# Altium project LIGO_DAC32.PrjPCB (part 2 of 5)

## Sheet LD32_FPGA.SchDoc: FPGA Top
size C; SheetNumber: 8; SheetTotal: 17
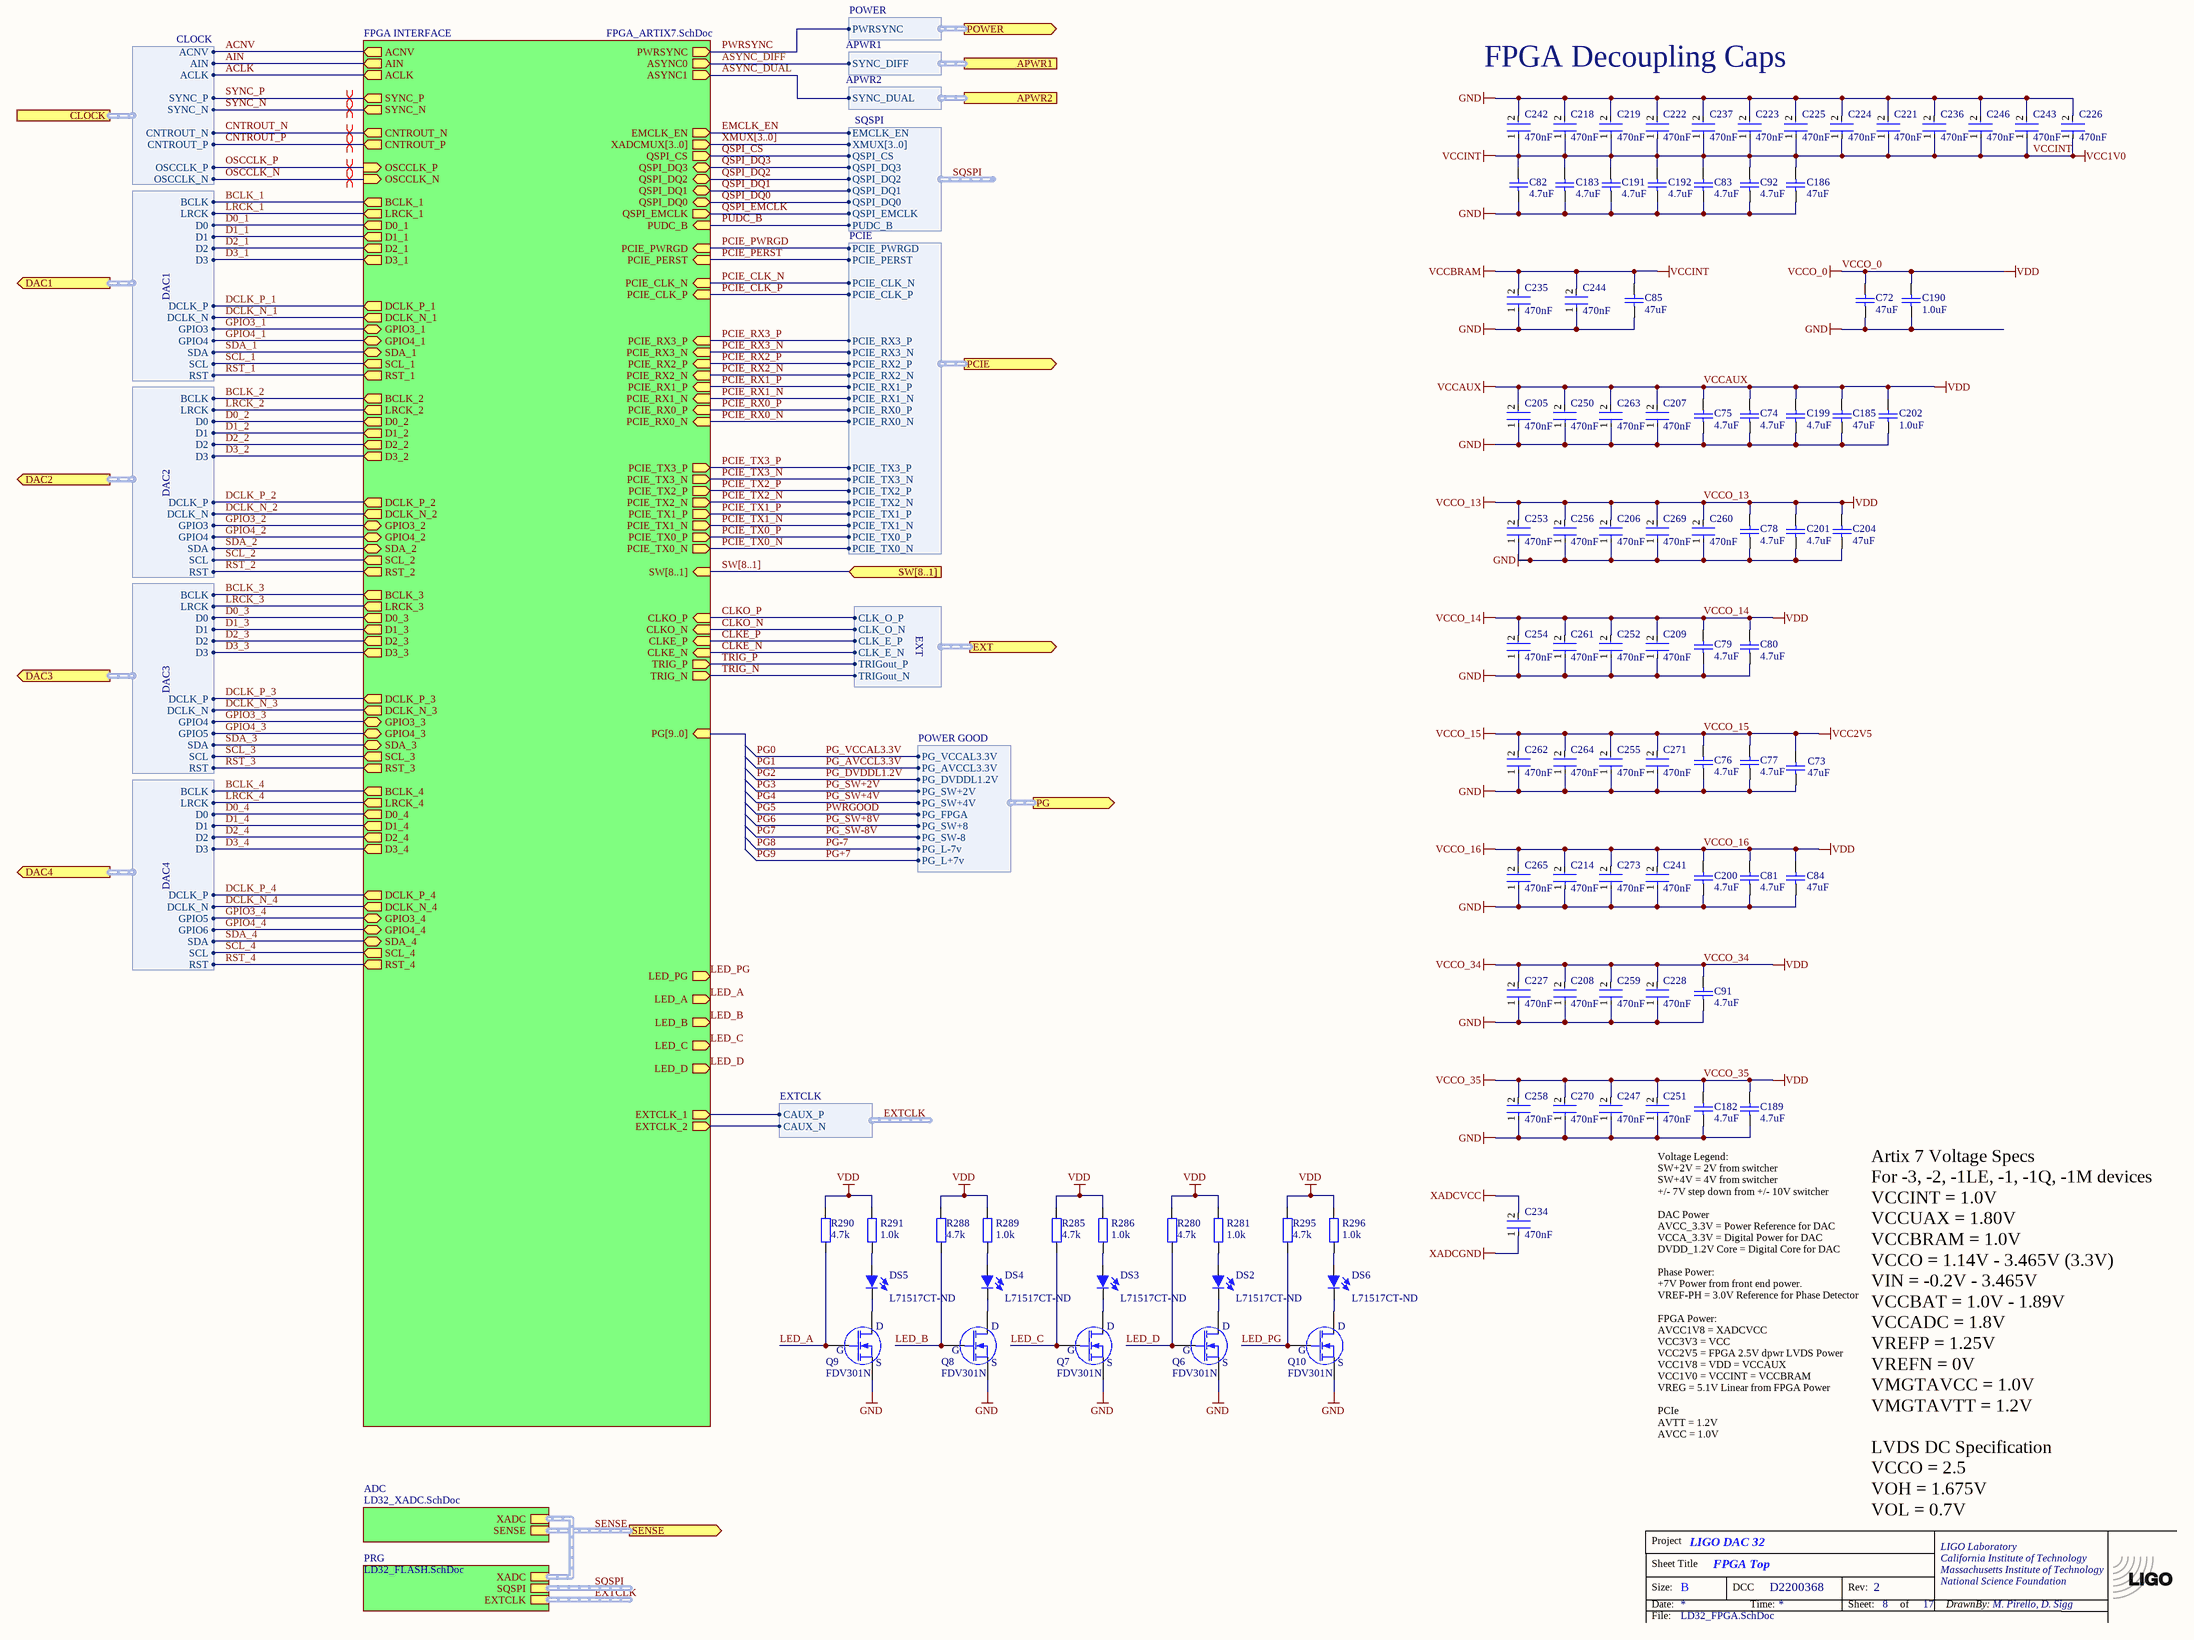
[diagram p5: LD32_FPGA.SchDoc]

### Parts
(Parts that share a designator on the sheet are numbered #1, #2 ... from top to bottom, then left to right.)
*?#3  TitleBlock  (value not drawn)  (graphical)
C72  47uF  [CC3216-1206]
C73  47uF  [CC3216-1206]
C74  4.7uF  [CC1608-0603]
C75  4.7uF  [CC1608-0603]
C76  4.7uF  [CC1608-0603]
C77  4.7uF  [CC1608-0603]
C78  4.7uF  [CC1608-0603]
C79  4.7uF  [CC1608-0603]
C80  4.7uF  [CC1608-0603]
C81  4.7uF  [CC1608-0603]
C82  4.7uF  [CC1608-0603]
C83  4.7uF  [CC1608-0603]
C84  47uF  [CC3216-1206]
C85  47uF  [CC3216-1206]
C91  4.7uF  [CC1608-0603]
C92  4.7uF  [CC1608-0603]
C182  4.7uF  [CC1608-0603]
C183  4.7uF  [CC1608-0603]
C185  47uF  [CC3216-1206]
C186  47uF  [CC3216-1206]
C189  4.7uF  [CC1608-0603]
C190  1.0uF  [CC1608-0603]
C191  4.7uF  [CC1608-0603]
C192  4.7uF  [CC1608-0603]
C199  4.7uF  [CC1608-0603]
C200  4.7uF  [CC1608-0603]
C201  4.7uF  [CC1608-0603]
C202  1.0uF  [CC1608-0603]
C204  47uF  [CC3216-1206]
C205  470nF  [FP-CL03-IPC_B]
C206  470nF  [FP-CL03-IPC_B]
C207  470nF  [FP-CL03-IPC_B]
C208  470nF  [FP-CL03-IPC_B]
C209  470nF  [FP-CL03-IPC_B]
C214  470nF  [FP-CL03-IPC_B]
C218  470nF  [FP-CL03-IPC_B]
C219  470nF  [FP-CL03-IPC_B]
C221  470nF  [FP-CL03-IPC_B]
C222  470nF  [FP-CL03-IPC_B]
C223  470nF  [FP-CL03-IPC_B]
C224  470nF  [FP-CL03-IPC_B]
C225  470nF  [FP-CL03-IPC_B]
C226  470nF  [FP-CL03-IPC_B]
C227  470nF  [FP-CL03-IPC_B]
C228  470nF  [FP-CL03-IPC_B]
C234  470nF  [FP-CL03-IPC_B]
C235  470nF  [FP-CL03-IPC_B]
C236  470nF  [FP-CL03-IPC_B]
C237  470nF  [FP-CL03-IPC_B]
C241  470nF  [FP-CL03-IPC_B]
C242  470nF  [FP-CL03-IPC_B]
C243  470nF  [FP-CL03-IPC_B]
C244  470nF  [FP-CL03-IPC_B]
C246  470nF  [FP-CL03-IPC_B]
C247  470nF  [FP-CL03-IPC_B]
C250  470nF  [FP-CL03-IPC_B]
C251  470nF  [FP-CL03-IPC_B]
C252  470nF  [FP-CL03-IPC_B]
C253  470nF  [FP-CL03-IPC_B]
C254  470nF  [FP-CL03-IPC_B]
C255  470nF  [FP-CL03-IPC_B]
C256  470nF  [FP-CL03-IPC_B]
C258  470nF  [FP-CL03-IPC_B]
C259  470nF  [FP-CL03-IPC_B]
C260  470nF  [FP-CL03-IPC_B]
C261  470nF  [FP-CL03-IPC_B]
C262  470nF  [FP-CL03-IPC_B]
C263  470nF  [FP-CL03-IPC_B]
C264  470nF  [FP-CL03-IPC_B]
C265  470nF  [FP-CL03-IPC_B]
C269  470nF  [FP-CL03-IPC_B]
C270  470nF  [FP-CL03-IPC_B]
C271  470nF  [FP-CL03-IPC_B]
C273  470nF  [FP-CL03-IPC_B]
DS2  Supplier Part Number 1: L71517CT-ND  [LED-0805]  (hidden comment: LED)
DS3  Supplier Part Number 1: L71517CT-ND  [LED-0805]  (hidden comment: LED)
DS4  Supplier Part Number 1: L71517CT-ND  [LED-0805]  (hidden comment: LED)
DS5  Supplier Part Number 1: L71517CT-ND  [LED-0805]  (hidden comment: LED)
DS6  Supplier Part Number 1: L71517CT-ND  [LED-0805]  (hidden comment: LED)
Q6  FDV301N  [SO-G3/C2.25]
Q7  FDV301N  [SO-G3/C2.25]
Q8  FDV301N  [SO-G3/C2.25]
Q9  FDV301N  [SO-G3/C2.25]
Q10  FDV301N  [SO-G3/C2.25]
R280  4.7k  [CR1005-0402]
R281  1.0k  [CR1005-0402]
R285  4.7k  [CR1005-0402]
R286  1.0k  [CR1005-0402]
R288  4.7k  [CR1005-0402]
R289  1.0k  [CR1005-0402]
R290  4.7k  [CR1005-0402]
R291  1.0k  [CR1005-0402]
R295  4.7k  [CR1005-0402]
R296  1.0k  [CR1005-0402]

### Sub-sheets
ADC = LD32_XADC.SchDoc: XADC (harness XADC), SENSE (harness SENSE)
FPGA INTERFACE = FPGA_ARTIX7.SchDoc: SW[8..1] (in), XADCMUX[3..0] (out), PWRSYNC (out), QSPI_DQ0 (bidir), QSPI_CS (out), QSPI_DQ2 (bidir), QSPI_DQ3 (bidir), QSPI_DQ1 (bidir), QSPI_EMCLK (out), PUDC_B (in), EMCLK_EN (out), PCIE_PWRGD (in), PCIE_PERST (in), PCIE_CLK_N (in), PCIE_CLK_P (in), PCIE_RX0_N (in), PCIE_TX0_P (out), PCIE_RX0_P (in), PCIE_TX0_N (out), PCIE_TX3_P (out), PCIE_TX2_P (out), PCIE_TX1_P (out), PCIE_TX3_N (out), PCIE_TX2_N (out), PCIE_TX1_N (out), PCIE_RX1_P (in), PCIE_RX2_P (in), PCIE_RX3_P (in), PCIE_RX1_N (in), PCIE_RX2_N (in), PCIE_RX3_N (in), ACNV (out), AIN (out), ACLK (out), SYNC_P (out), SYNC_N (out), CNTROUT_N (out), CNTROUT_P (out), OSCCLK_P (in), OSCCLK_N (in), BCLK_1 (out), LRCK_1 (out), D0_1 (out), DCLK_P_1 (out), DCLK_N_1 (out), SDA_1 (bidir), SCL_1 (out), RST_1 (out), GPIO4_1 (bidir), GPIO3_1 (bidir), D1_1 (out), D2_1 (out), D3_1 (out), BCLK_2 (out), LRCK_2 (out), D0_2 (out), DCLK_P_2 (out), DCLK_N_2 (out), SDA_2 (bidir), SCL_2 (out), RST_2 (out), GPIO4_2 (bidir), GPIO3_2 (bidir), D1_2 (out), D2_2 (out), D3_2 (out), BCLK_3 (out), LRCK_3 (out), D0_3 (out), DCLK_P_3 (out), DCLK_N_3 (out), SDA_3 (bidir), SCL_3 (out), RST_3 (out), GPIO4_3 (bidir), GPIO3_3 (bidir), D1_3 (out), D2_3 (out), D3_3 (out), BCLK_4 (out), LRCK_4 (out), D0_4 (out), DCLK_P_4 (out), DCLK_N_4 (out), SDA_4 (bidir), SCL_4 (out), RST_4 (out), GPIO4_4 (bidir), GPIO3_4 (bidir), D1_4 (out), D2_4 (out), D3_4 (out), CLKO_P (in), CLKO_N (in), CLKE_P (in), CLKE_N (in), TRIG_P (out), TRIG_N (out), ASYNC0 (out), ASYNC1 (out), PG[9..0] (in), LED_A (out), LED_PG (out), LED_B (out), LED_C (out), LED_D (out), EXTCLK_1 (out), EXTCLK_2 (out)
PRG = LD32_FLASH.SchDoc: SQSPI (harness SQSPI), XADC (harness XADC), EXTCLK (harness SQSPI)

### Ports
APWR1 (harness APWR1), APWR2 (harness APWR2), CLOCK (harness CLOCK), DAC1 (out, harness DAC1), DAC2 (out, harness DAC2), DAC3 (out, harness DAC3), DAC4 (out, harness DAC4), EXT (out, harness EXT), PCIE (out, harness PCIE), PG (out, harness Power good), POWER (out, harness POWER), SENSE (out, harness Power good), SW[8..1] (in)

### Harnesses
SQSPI: QSPI_CS, QSPI_DQ3, QSPI_DQ2, QSPI_DQ1, QSPI_DQ0, QSPI_EMCLK, PUDC_B, XMUX[3..0], EMCLK_EN
DAC1: BCLK, LRCK, D0, D1, D2, D3, SCL, SDA, RST, GPIO4, GPIO3, DCLK_N, DCLK_P
DAC2: BCLK, LRCK, D0, D1, D2, D3, SCL, SDA, RST, GPIO4, GPIO3, DCLK_N, DCLK_P
DAC3: BCLK, LRCK, D1, D2, D3, SCL, SDA, RST, GPIO5, GPIO4, DCLK_N, DCLK_P, D0
DAC4: BCLK, LRCK, D2, D3, SCL, SDA, RST, GPIO6, GPIO5, DCLK_N, DCLK_P, D1, D0
APWR1: SYNC_DIFF
APWR2: SYNC_DUAL
POWER GOOD: PG_VCCAL3.3V, PG_AVCCL3.3V, PG_DVDDL1.2V, PG_SW+2V, PG_SW+4V, PG_FPGA, PG_SW+8, PG_SW-8, PG_L-7v, PG_L+7v
CLOCK: OSCCLK_N, OSCCLK_P, CNTROUT_N, CNTROUT_P, SYNC_N, SYNC_P, ACLK, ACNV, AIN
PCIE: PCIE_CLK_N, PCIE_CLK_P, PCIE_RX0_N, PCIE_RX0_P, PCIE_TX0_N, PCIE_TX0_P, PCIE_PERST, PCIE_PWRGD, PCIE_TX1_N, PCIE_TX1_P, PCIE_TX2_P, PCIE_TX2_N, PCIE_TX3_P, PCIE_TX3_N, PCIE_RX1_N, PCIE_RX1_P, PCIE_RX2_N, PCIE_RX2_P, PCIE_RX3_N, PCIE_RX3_P
EXT: CLK_O_N, CLK_E_P, CLK_E_N, CLK_O_P, TRIGout_P, TRIGout_N
POWER: PWRSYNC
EXTCLK: CAUX_P, CAUX_N

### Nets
GND: C72.1 C73.1 C74.1 C75.1 C76.1 C77.1 C78.1 C79.1 C80.1 C81.1 C82.1 C83.1 C84.1 C85.1 C91.1 C92.1 C182.1 C183.1 C185.1 C186.1 C189.1 C190.1 C191.1 C192.1 C199.1 C200.1 C201.1 C202.1 C204.1 C205.1 C206.1 C207.1 C208.1 C209.1 C214.1 C218.2 C219.2 C221.2 C222.2 C223.2 C224.2 C225.2 C226.2 C227.1 C228.1 C235.1 C236.2 C237.2 C241.1 C242.2 C243.2 C244.1 C246.2 C247.1 C250.1 C251.1 C252.1 C253.1 C254.1 C255.1 C256.1 C258.1 C259.1 C260.1 C261.1 C262.1 C263.1 C264.1 C265.1 C269.1 C270.1 C271.1 C273.1 Q6.2(S) Q7.2(S) Q8.2(S) Q9.2(S) Q10.2(S)
VCC1V0: C82.2 C83.2 C85.2 C92.2 C183.2 C186.2 C191.2 C192.2 C218.1 C219.1 C221.1 C222.1 C223.1 C224.1 C225.1 C226.1 C235.2 C236.1 C237.1 C242.1 C243.1 C244.2 C246.1  [also labelled VCCBRAM, VCCINT]
VCC2V5: C73.2 C76.2 C77.2 C255.2 C262.2 C264.2 C271.2  [also labelled VCCO_15]
VCCAUX: C72.2 C74.2 C75.2 C78.2 C79.2 C80.2 C81.2 C84.2 C91.2 C182.2 C185.2 C189.2 C190.2 C199.2 C200.2 C201.2 C202.2 C204.2 C205.2 C206.2 C207.2 C208.2 C209.2 C214.2 C227.2 C228.2 C241.2 C247.2 C250.2 C251.2 C252.2 C253.2 C254.2 C256.2 C258.2 C259.2 C260.2 C261.2 C263.2 C265.2 C269.2 C270.2 C273.2 R280.2 R281.1 R285.2 R286.1 R288.2 R289.1 R290.2 R291.1 R295.2 R296.1  [also labelled VCCO_0, VCCO_13, VCCO_14, VCCO_16, VCCO_34, VCCO_35, VDD]
XADCGND: C234.1
XADCVCC: C234.2
ACLK: sheet FPGA INTERFACE/ACLK, port CLOCK.ACLK  [project net CLOCK.ACLK]
ACNV: sheet FPGA INTERFACE/ACNV, port CLOCK.ACNV  [project net CLOCK.ACNV]
AIN: sheet FPGA INTERFACE/AIN, port CLOCK.AIN  [project net CLOCK.AIN]
ASYNC_DIFF: sheet FPGA INTERFACE/ASYNC0, port APWR1.SYNC_DIFF  [project net APWR1.SYNC_DIFF]
ASYNC_DUAL: sheet FPGA INTERFACE/ASYNC1, port APWR2.SYNC_DUAL  [project net APWR2.SYNC_DUAL]
BCLK_1: sheet FPGA INTERFACE/BCLK_1, port DAC1.BCLK  [project net DAC1.BCLK]
BCLK_2: sheet FPGA INTERFACE/BCLK_2, port DAC2.BCLK  [project net DAC2.BCLK]
BCLK_3: sheet FPGA INTERFACE/BCLK_3, port DAC3.BCLK  [project net DAC3.BCLK]
BCLK_4: sheet FPGA INTERFACE/BCLK_4, port DAC4.BCLK  [project net DAC4.BCLK]
CLKE_N: sheet FPGA INTERFACE/CLKE_N, port EXT.CLK_E_N
CLKE_P: sheet FPGA INTERFACE/CLKE_P, port EXT.CLK_E_P
CLKO_N: sheet FPGA INTERFACE/CLKO_N, port EXT.CLK_O_N
CLKO_P: sheet FPGA INTERFACE/CLKO_P, port EXT.CLK_O_P
CNTROUT_N: sheet FPGA INTERFACE/CNTROUT_N, port CLOCK.CNTROUT_N  [project net CLOCK.CNTROUT_N]
CNTROUT_P: sheet FPGA INTERFACE/CNTROUT_P, port CLOCK.CNTROUT_P  [project net CLOCK.CNTROUT_P]
D0_1: sheet FPGA INTERFACE/D0_1, port DAC1.D0  [project net DAC1.D0]
D0_2: sheet FPGA INTERFACE/D0_2, port DAC2.D0  [project net DAC2.D0]
D0_3: sheet FPGA INTERFACE/D0_3, port DAC3.D0  [project net DAC3.D0]
D0_4: sheet FPGA INTERFACE/D0_4, port DAC4.D0  [project net DAC4.D0]
D1_1: sheet FPGA INTERFACE/D1_1, port DAC1.D1  [project net DAC1.D1]
D1_2: sheet FPGA INTERFACE/D1_2, port DAC2.D1  [project net DAC2.D1]
D1_3: sheet FPGA INTERFACE/D1_3, port DAC3.D1  [project net DAC3.D1]
D1_4: sheet FPGA INTERFACE/D1_4, port DAC4.D1  [project net DAC4.D1]
D2_1: sheet FPGA INTERFACE/D2_1, port DAC1.D2  [project net DAC1.D2]
D2_2: sheet FPGA INTERFACE/D2_2, port DAC2.D2  [project net DAC2.D2]
D2_3: sheet FPGA INTERFACE/D2_3, port DAC3.D2  [project net DAC3.D2]
D2_4: sheet FPGA INTERFACE/D2_4, port DAC4.D2  [project net DAC4.D2]
D3_1: sheet FPGA INTERFACE/D3_1, port DAC1.D3  [project net DAC1.D3]
D3_2: sheet FPGA INTERFACE/D3_2, port DAC2.D3  [project net DAC2.D3]
D3_3: sheet FPGA INTERFACE/D3_3, port DAC3.D3  [project net DAC3.D3]
D3_4: sheet FPGA INTERFACE/D3_4, port DAC4.D3  [project net DAC4.D3]
DCLK_N_1: sheet FPGA INTERFACE/DCLK_N_1, port DAC1.DCLK_N  [project net DAC1.DCLK_N]
DCLK_N_2: sheet FPGA INTERFACE/DCLK_N_2, port DAC2.DCLK_N  [project net DAC2.DCLK_N]
DCLK_N_3: sheet FPGA INTERFACE/DCLK_N_3, port DAC3.DCLK_N  [project net DAC3.DCLK_N]
DCLK_N_4: sheet FPGA INTERFACE/DCLK_N_4, port DAC4.DCLK_N  [project net DAC4.DCLK_N]
DCLK_P_1: sheet FPGA INTERFACE/DCLK_P_1, port DAC1.DCLK_P  [project net DAC1.DCLK_P]
DCLK_P_2: sheet FPGA INTERFACE/DCLK_P_2, port DAC2.DCLK_P  [project net DAC2.DCLK_P]
DCLK_P_3: sheet FPGA INTERFACE/DCLK_P_3, port DAC3.DCLK_P  [project net DAC3.DCLK_P]
DCLK_P_4: sheet FPGA INTERFACE/DCLK_P_4, port DAC4.DCLK_P  [project net DAC4.DCLK_P]
EMCLK_EN: sheet FPGA INTERFACE/EMCLK_EN, sheet PRG/SQSPI.EMCLK_EN  [project net SQSPI.EMCLK_EN]
EXTCLK.CAUX_N: sheet FPGA INTERFACE/EXTCLK_2, sheet PRG/EXTCLK.CAUX_N
EXTCLK.CAUX_P: sheet FPGA INTERFACE/EXTCLK_1, sheet PRG/EXTCLK.CAUX_P
GPIO3_1: sheet FPGA INTERFACE/GPIO3_1, port DAC1.GPIO3  [project net DAC1.GPIO3_]
GPIO3_2: sheet FPGA INTERFACE/GPIO3_2, port DAC2.GPIO3  [project net DAC2.GPIO3_]
GPIO3_3: sheet FPGA INTERFACE/GPIO3_3, port DAC3.GPIO4  [project net DAC3.GPIO4_]
GPIO3_4: sheet FPGA INTERFACE/GPIO3_4, port DAC4.GPIO5  [project net DAC4.GPIO5]
GPIO4_1: sheet FPGA INTERFACE/GPIO4_1, port DAC1.GPIO4  [project net DAC1.GPIO4_]
GPIO4_2: sheet FPGA INTERFACE/GPIO4_2, port DAC2.GPIO4  [project net DAC2.GPIO4_]
GPIO4_3: sheet FPGA INTERFACE/GPIO4_3, port DAC3.GPIO5  [project net DAC3.GPIO5]
GPIO4_4: sheet FPGA INTERFACE/GPIO4_4, port DAC4.GPIO6  [project net DAC4.GPIO6]
LED_A: Q9.1(G) R290.1 ; sheet FPGA INTERFACE/LED_A
LED_B: Q8.1(G) R288.1 ; sheet FPGA INTERFACE/LED_B
LED_C: Q7.1(G) R285.1 ; sheet FPGA INTERFACE/LED_C
LED_D: Q6.1(G) R280.1 ; sheet FPGA INTERFACE/LED_D
LED_PG: Q10.1(G) R295.1 ; sheet FPGA INTERFACE/LED_PG
LRCK_1: sheet FPGA INTERFACE/LRCK_1, port DAC1.LRCK  [project net DAC1.LRCK]
LRCK_2: sheet FPGA INTERFACE/LRCK_2, port DAC2.LRCK  [project net DAC2.LRCK]
LRCK_3: sheet FPGA INTERFACE/LRCK_3, port DAC3.LRCK  [project net DAC3.LRCK]
LRCK_4: sheet FPGA INTERFACE/LRCK_4, port DAC4.LRCK  [project net DAC4.LRCK]
OSCCLK_N: sheet FPGA INTERFACE/OSCCLK_N, port CLOCK.OSCCLK_N  [project net CLOCK.OSCCLK_N]
OSCCLK_P: sheet FPGA INTERFACE/OSCCLK_P, port CLOCK.OSCCLK_P  [project net CLOCK.OSCCLK_P]
PCIE_CLK_N: sheet FPGA INTERFACE/PCIE_CLK_N, port PCIE.PCIE_CLK_N  [project net PCIE.PCIE_CLK_N]
PCIE_CLK_P: sheet FPGA INTERFACE/PCIE_CLK_P, port PCIE.PCIE_CLK_P  [project net PCIE.PCIE_CLK_P]
PCIE_PERST: sheet FPGA INTERFACE/PCIE_PERST, port PCIE.PCIE_PERST  [project net PCIE.PCIE_PERST]
PCIE_PWRGD: sheet FPGA INTERFACE/PCIE_PWRGD, port PCIE.PCIE_PWRGD  [project net PCIE.PCIE_PWRGD]
PCIE_RX0_N: sheet FPGA INTERFACE/PCIE_RX0_N, port PCIE.PCIE_RX0_N  [project net PCIE.PCIE_RX0_N]
PCIE_RX0_P: sheet FPGA INTERFACE/PCIE_RX0_P, port PCIE.PCIE_RX0_P  [project net PCIE.PCIE_RX0_P]
PCIE_RX1_N: sheet FPGA INTERFACE/PCIE_RX1_N, port PCIE.PCIE_RX1_N  [project net PCIE.PCIE_RX1_N]
PCIE_RX1_P: sheet FPGA INTERFACE/PCIE_RX1_P, port PCIE.PCIE_RX1_P  [project net PCIE.PCIE_RX1_P]
PCIE_RX2_N: sheet FPGA INTERFACE/PCIE_RX2_N, port PCIE.PCIE_RX2_N  [project net PCIE.PCIE_RX2_N]
PCIE_RX2_P: sheet FPGA INTERFACE/PCIE_RX2_P, port PCIE.PCIE_RX2_P  [project net PCIE.PCIE_RX2_P]
PCIE_RX3_N: sheet FPGA INTERFACE/PCIE_RX3_N, port PCIE.PCIE_RX3_N  [project net PCIE.PCIE_RX3_N]
PCIE_RX3_P: sheet FPGA INTERFACE/PCIE_RX3_P, port PCIE.PCIE_RX3_P  [project net PCIE.PCIE_RX3_P]
PCIE_TX0_N: sheet FPGA INTERFACE/PCIE_TX0_N, port PCIE.PCIE_TX0_N  [project net PCIE.PCIE_TX0_N]
PCIE_TX0_P: sheet FPGA INTERFACE/PCIE_TX0_P, port PCIE.PCIE_TX0_P  [project net PCIE.PCIE_TX0_P]
PCIE_TX1_N: sheet FPGA INTERFACE/PCIE_TX1_N, port PCIE.PCIE_TX1_N  [project net PCIE.PCIE_TX1_N]
PCIE_TX1_P: sheet FPGA INTERFACE/PCIE_TX1_P, port PCIE.PCIE_TX1_P  [project net PCIE.PCIE_TX1_P]
PCIE_TX2_N: sheet FPGA INTERFACE/PCIE_TX2_N, port PCIE.PCIE_TX2_N  [project net PCIE.PCIE_TX2_N]
PCIE_TX2_P: sheet FPGA INTERFACE/PCIE_TX2_P, port PCIE.PCIE_TX2_P  [project net PCIE.PCIE_TX2_P]
PCIE_TX3_N: sheet FPGA INTERFACE/PCIE_TX3_N, port PCIE.PCIE_TX3_N  [project net PCIE.PCIE_TX3_N]
PCIE_TX3_P: sheet FPGA INTERFACE/PCIE_TX3_P, port PCIE.PCIE_TX3_P  [project net PCIE.PCIE_TX3_P]
PUDC_B: sheet FPGA INTERFACE/PUDC_B, sheet PRG/SQSPI.PUDC_B  [project net SQSPI.PUDC_B]
PWRSYNC: sheet FPGA INTERFACE/PWRSYNC, port POWER.PWRSYNC  [project net POWER.PWRSYNC]
QSPI_CS: sheet FPGA INTERFACE/QSPI_CS, sheet PRG/SQSPI.QSPI_CS  [project net SQSPI.QSPI_CS]
QSPI_DQ0: sheet FPGA INTERFACE/QSPI_DQ0, sheet PRG/SQSPI.QSPI_DQ0  [project net SQSPI.QSPI_DQ0]
QSPI_DQ1: sheet FPGA INTERFACE/QSPI_DQ1, sheet PRG/SQSPI.QSPI_DQ1  [project net SQSPI.QSPI_DQ1]
QSPI_DQ2: sheet FPGA INTERFACE/QSPI_DQ2, sheet PRG/SQSPI.QSPI_DQ2  [project net SQSPI.QSPI_DQ2]
QSPI_DQ3: sheet FPGA INTERFACE/QSPI_DQ3, sheet PRG/SQSPI.QSPI_DQ3  [project net SQSPI.QSPI_DQ3]
QSPI_EMCLK: sheet FPGA INTERFACE/QSPI_EMCLK, sheet PRG/SQSPI.QSPI_EMCLK  [project net SQSPI.QSPI_EMCLK]
RST_1: sheet FPGA INTERFACE/RST_1, port DAC1.RST  [project net DAC1.RST]
RST_2: sheet FPGA INTERFACE/RST_2, port DAC2.RST  [project net DAC2.RST]
RST_3: sheet FPGA INTERFACE/RST_3, port DAC3.RST  [project net DAC3.RST]
RST_4: sheet FPGA INTERFACE/RST_4, port DAC4.RST  [project net DAC4.RST]
SCL_1: sheet FPGA INTERFACE/SCL_1, port DAC1.SCL  [project net DAC1.SCL]
SCL_2: sheet FPGA INTERFACE/SCL_2, port DAC2.SCL  [project net DAC2.SCL]
SCL_3: sheet FPGA INTERFACE/SCL_3, port DAC3.SCL  [project net DAC3.SCL]
SCL_4: sheet FPGA INTERFACE/SCL_4, port DAC4.SCL  [project net DAC4.SCL]
SDA_1: sheet FPGA INTERFACE/SDA_1, port DAC1.SDA  [project net DAC1.SDA]
SDA_2: sheet FPGA INTERFACE/SDA_2, port DAC2.SDA  [project net DAC2.SDA]
SDA_3: sheet FPGA INTERFACE/SDA_3, port DAC3.SDA  [project net DAC3.SDA]
SDA_4: sheet FPGA INTERFACE/SDA_4, port DAC4.SDA  [project net DAC4.SDA]
SYNC_N: sheet FPGA INTERFACE/SYNC_N, port CLOCK.SYNC_N  [project net CLOCK.SYNC_N]
SYNC_P: sheet FPGA INTERFACE/SYNC_P, port CLOCK.SYNC_P  [project net CLOCK.SYNC_P]
TRIG_N: sheet FPGA INTERFACE/TRIG_N, port EXT.TRIGout_N  [project net EXT.TRIGout_N]
TRIG_P: sheet FPGA INTERFACE/TRIG_P, port EXT.TRIGout_P  [project net EXT.TRIGout_P]
NetDS2_1: DS2.1(K) Q6.3(D)
NetDS2_2: DS2.2(A) R281.2
NetDS3_1: DS3.1(K) Q7.3(D)
NetDS3_2: DS3.2(A) R286.2
NetDS4_1: DS4.1(K) Q8.3(D)
NetDS4_2: DS4.2(A) R289.2
NetDS5_1: DS5.1(K) Q9.3(D)
NetDS5_2: DS5.2(A) R291.2
NetDS6_1: DS6.1(K) Q10.3(D)
NetDS6_2: DS6.2(A) R296.2

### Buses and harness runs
bus SW[8..1] = port SW[8..1] = sheet FPGA INTERFACE/SW[8..1]
bus XMUX[3..0] = sheet FPGA INTERFACE/XADCMUX[3..0]
harness EXTCLK = sheet PRG/EXTCLK
harness SENSE = port SENSE = sheet ADC/SENSE
harness sheet ADC/XADC = sheet PRG/XADC
harness SQSPI = sheet PRG/SQSPI

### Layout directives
differential pair: CLOCK.CNTROUT_N, CLOCK.CNTROUT_P, CLOCK.OSCCLK_N, CLOCK.OSCCLK_P, CLOCK.SYNC_N, CLOCK.SYNC_P

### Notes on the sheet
- FPGA Decoupling Caps
- Voltage Legend:
  SW+2V = 2V from switcher
  SW+4V = 4V from switcher
  +/- 7V step down from +/- 10V switcher
  DAC Power
  AVCC_3.3V = Power Reference for DAC
  VCCA_3.3V = Digital Power for DAC
  DVDD_1.2V Core = Digital Core for DAC
  Phase Power:
  +7V Power from front end power.
  VREF-PH = 3.0V Reference for Phase Detector
  FPGA Power:
  AVCC1V8 = XADCVCC
  VCC3V3 = VCC
  VCC2V5 = FPGA 2.5V dpwr LVDS Power
  VCC1V8 = VDD = VCCAUX
  VCC1V0 = VCCINT = VCCBRAM
  VREG = 5.1V Linear from FPGA Power
  PCIe
  AVTT = 1.2V
  AVCC = 1.0V
- Artix 7 Voltage Specs
  For -3, -2, -1LE, -1, -1Q, -1M devices
  VCCINT = 1.0V
  VCCUAX = 1.80V
  VCCBRAM = 1.0V
  VCCO = 1.14V - 3.465V (3.3V)
  VIN = -0.2V - 3.465V
  VCCBAT = 1.0V - 1.89V
  VCCADC = 1.8V
  VREFP = 1.25V
  VREFN = 0V
  VMGTAVCC = 1.0V
  VMGTAVTT = 1.2V
  LVDS DC Specification
  VCCO = 2.5
  VOH = 1.675V
  VOL = 0.7V

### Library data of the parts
C72 C73 C84 C85 C185 C186 C204 = ChipCap: C1206 47uF; Part Number: C3216X5R1E476M160DC
C74-C83 C91 C92 C182 C183 C189 C191 C192 C199-C201 = ChipCap: C0603 4.7uF; Part Number: CL10B475KQ8NQNC
C190 C202 = ChipCap: C0603 1.0uF; Part Number: CL10B105KA8NNNC
C205-C209 C214 C218 C219 C221-C228 C234-C237 C241-C244 C246 C247 C250-C256 C258-C265 C269-C271 C273 = CMP-2010-00306-2: Cap Ceramic 470nF 4V X5R ±20% Pad SMD 0201 +85°C T/R; Part Number: LMK063BBJ474MPLF
DS2-DS6 = LED: Panel mount LED
Q6-Q10 = FDV301N: FDV301N, Digital FET, N-channel, SOT23; Part Number: FDV301NCT-ND
R280 R285 R288 R290 R295 = ChipRes1: R0402 4.7k; Part Number: ERA-2AED472X
R281 R286 R289 R291 R296 = ChipRes1: R0402 1.0k; Part Number: ERA-2AEB102X

## Sheet FPGA_ARTIX7.SchDoc: FPGA
size C; Organization: Altium Limited; Address1: L3, 12a Rodborough Rd; Address2: Frenchs Forest; Address3: NSW; Address4: Australia 2086; SheetNumber: 11; SheetTotal: 17
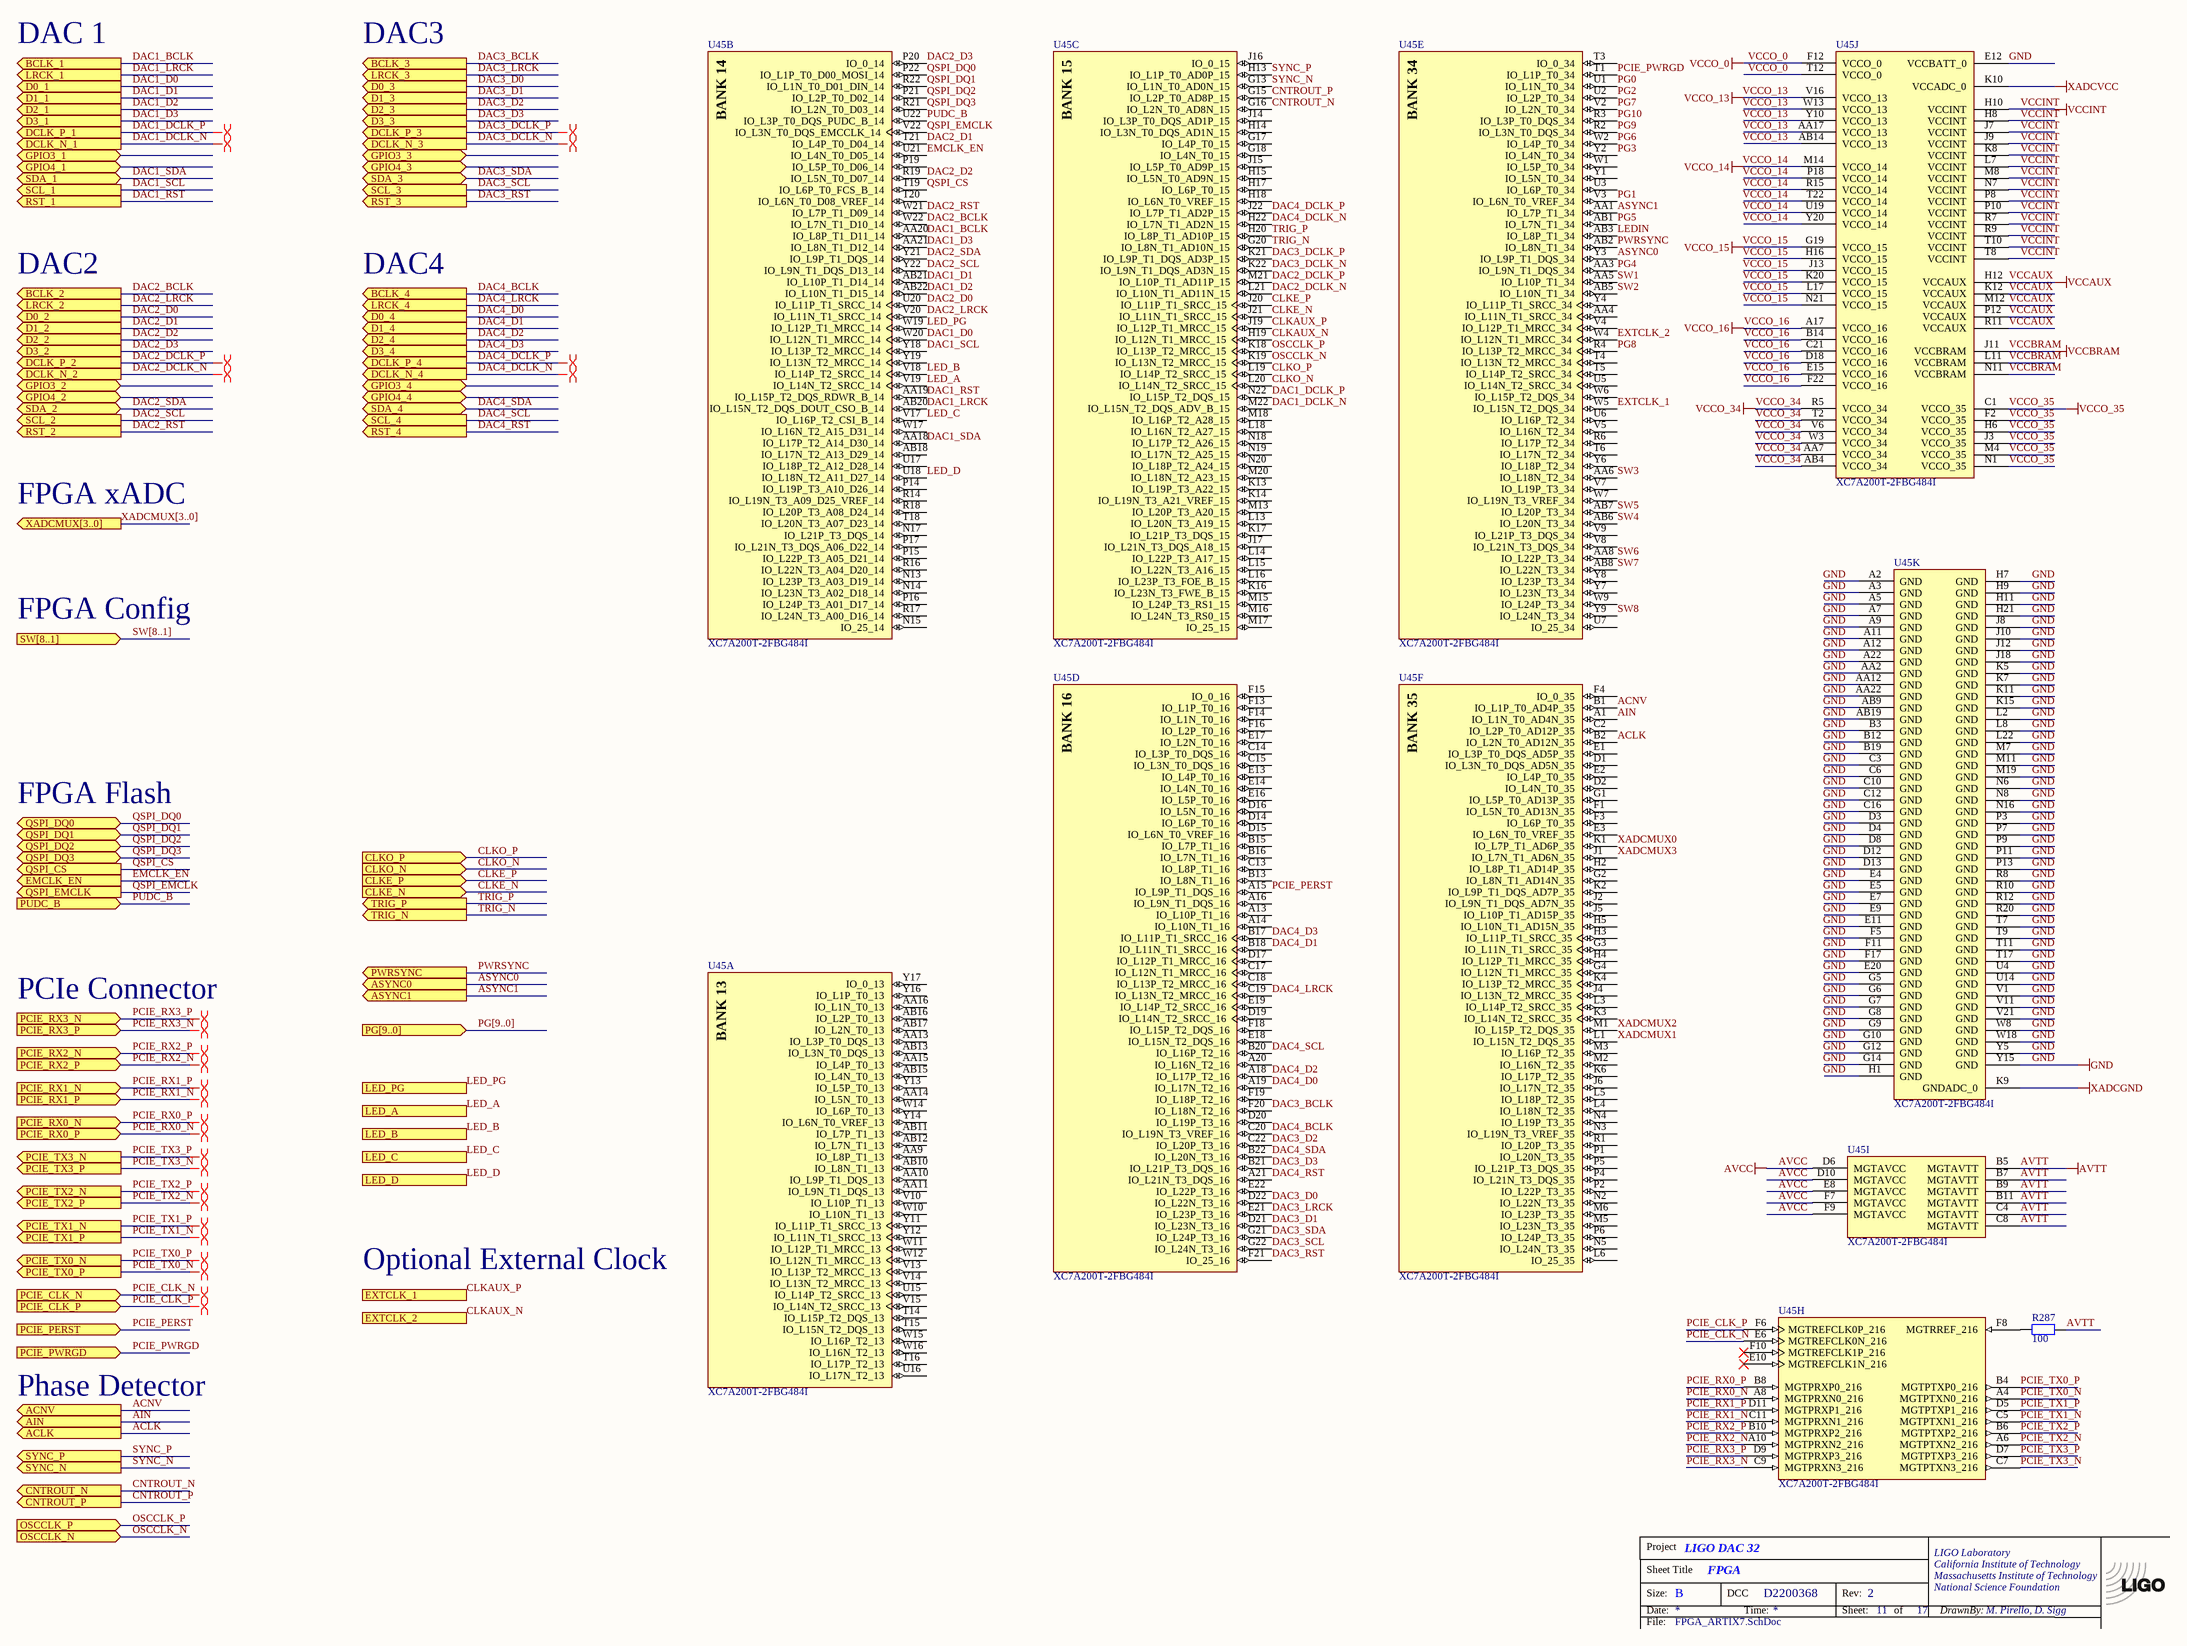
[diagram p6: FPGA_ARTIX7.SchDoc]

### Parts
(Parts that share a designator on the sheet are numbered #1, #2 ... from top to bottom, then left to right.)
*?#4  TitleBlock  (value not drawn)  (graphical)
R287  100  [CR1005-0402]
U45  XC7A200T-2FBG484I  [FBG484]  (parts A,B,C,D,E,F,H,I,J,K of 11)

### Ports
ACLK (out), ACNV (out), AIN (out), ASYNC0 (out), ASYNC1 (out), BCLK_1 (out), BCLK_2 (out), BCLK_3 (out), BCLK_4 (out), CLKE_N (in), CLKE_P (in), CLKO_N (in), CLKO_P (in), CNTROUT_N (out), CNTROUT_P (out), D0_1 (out), D0_2 (out), D0_3 (out), D0_4 (out), D1_1 (out), D1_2 (out), D1_3 (out), D1_4 (out), D2_1 (out), D2_2 (out), D2_3 (out), D2_4 (out), D3_1 (out), D3_2 (out), D3_3 (out), D3_4 (out), DCLK_N_1 (out), DCLK_N_2 (out), DCLK_N_3 (out), DCLK_N_4 (out), DCLK_P_1 (out), DCLK_P_2 (out), DCLK_P_3 (out), DCLK_P_4 (out), EMCLK_EN (out), EXTCLK_1 (out), EXTCLK_2 (out), GPIO3_1 (bidir), GPIO3_2 (bidir), GPIO3_3 (bidir), GPIO3_4 (bidir), GPIO4_1 (bidir), GPIO4_2 (bidir), GPIO4_3 (bidir), GPIO4_4 (bidir), LED_A (out), LED_B (out), LED_C (out), LED_D (out), LED_PG (out), LRCK_1 (out), LRCK_2 (out), LRCK_3 (out), LRCK_4 (out), OSCCLK_N (in), OSCCLK_P (in), PCIE_CLK_N (in), PCIE_CLK_P (in), PCIE_PERST (in), PCIE_PWRGD (in), PCIE_RX0_N (in), PCIE_RX0_P (in), PCIE_RX1_N (in), PCIE_RX1_P (in), PCIE_RX2_N (in), PCIE_RX2_P (in), PCIE_RX3_N (in), PCIE_RX3_P (in), PCIE_TX0_N (out), PCIE_TX0_P (out), PCIE_TX1_N (out), PCIE_TX1_P (out), PCIE_TX2_N (out), PCIE_TX2_P (out), PCIE_TX3_N (out), PCIE_TX3_P (out), PG[9..0] (in), PUDC_B (in), PWRSYNC (out), QSPI_CS (out), QSPI_DQ0 (bidir), QSPI_DQ1 (bidir), QSPI_DQ2 (bidir), QSPI_DQ3 (bidir), QSPI_EMCLK (out), RST_1 (out), RST_2 (out), RST_3 (out), RST_4 (out), SCL_1 (out), SCL_2 (out), SCL_3 (out), SCL_4 (out), SDA_1 (bidir), SDA_2 (bidir), SDA_3 (bidir), SDA_4 (bidir), SW[8..1] (in), SYNC_N (out), SYNC_P (out), TRIG_N (out), TRIG_P (out), XADCMUX[3..0] (out)

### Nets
AVCC: U45.D6(MGTAVCC) U45.D10(MGTAVCC) U45.E8(MGTAVCC) U45.F7(MGTAVCC) U45.F9(MGTAVCC)
AVTT: R287.2 U45.B5(MGTAVTT) U45.B7(MGTAVTT) U45.B9(MGTAVTT) U45.B11(MGTAVTT) U45.C4(MGTAVTT) U45.C8(MGTAVTT)
GND: U45.A2(GND) U45.A3(GND) U45.A5(GND) U45.A7(GND) U45.A9(GND) U45.A11(GND) U45.A12(GND) U45.A22(GND) U45.AA2(GND) U45.AA12(GND) U45.AA22(GND) U45.AB9(GND) U45.AB19(GND) U45.B3(GND) U45.B12(GND) U45.B19(GND) U45.C3(GND) U45.C6(GND) U45.C10(GND) U45.C12(GND) U45.C16(GND) U45.D3(GND) U45.D4(GND) U45.D8(GND) U45.D12(GND) U45.D13(GND) U45.E4(GND) U45.E5(GND) U45.E7(GND) U45.E9(GND) U45.E11(GND) U45.E12(VCCBATT_0) U45.E20(GND) U45.F5(GND) U45.F11(GND) U45.F17(GND) U45.G5(GND) U45.G6(GND) U45.G7(GND) U45.G8(GND) U45.G9(GND) U45.G10(GND) U45.G12(GND) U45.G14(GND) U45.H1(GND) U45.H7(GND) U45.H9(GND) U45.H11(GND) U45.H21(GND) U45.J8(GND) U45.J10(GND) U45.J12(GND) U45.J18(GND) U45.K5(GND) U45.K7(GND) U45.K11(GND) U45.K15(GND) U45.L2(GND) U45.L8(GND) U45.L22(GND) U45.M7(GND) U45.M11(GND) U45.M19(GND) U45.N6(GND) U45.N8(GND) U45.N16(GND) U45.P3(GND) U45.P7(GND) U45.P9(GND) U45.P11(GND) U45.P13(GND) U45.R8(GND) U45.R10(GND) U45.R12(GND) U45.R20(GND) U45.T7(GND) U45.T9(GND) U45.T11(GND) U45.T17(GND) U45.U4(GND) U45.U14(GND) U45.V1(GND) U45.V11(GND) U45.V21(GND) U45.W8(GND) U45.W18(GND) U45.Y5(GND) U45.Y15(GND)
VCCAUX: U45.A17(VCCO_16) U45.AA7(VCCO_34) U45.AA17(VCCO_13) U45.AB4(VCCO_34) U45.AB14(VCCO_13) U45.B14(VCCO_16) U45.C1(VCCO_35) U45.C21(VCCO_16) U45.D18(VCCO_16) U45.E15(VCCO_16) U45.F2(VCCO_35) U45.F12(VCCO_0) U45.F22(VCCO_16) U45.H6(VCCO_35) U45.H12(VCCAUX) U45.J3(VCCO_35) U45.K12(VCCAUX) U45.M4(VCCO_35) U45.M12(VCCAUX) U45.M14(VCCO_14) U45.N1(VCCO_35) U45.P12(VCCAUX) U45.P18(VCCO_14) U45.R5(VCCO_34) U45.R11(VCCAUX) U45.R15(VCCO_14) U45.T2(VCCO_34) U45.T12(VCCO_0) U45.T22(VCCO_14) U45.U19(VCCO_14) U45.V6(VCCO_34) U45.V16(VCCO_13) U45.W3(VCCO_34) U45.W13(VCCO_13) U45.Y10(VCCO_13) U45.Y20(VCCO_14)  [also labelled VCCO_0, VCCO_13, VCCO_14, VCCO_16, VCCO_34, VCCO_35]
VCCBRAM: U45.H8(VCCINT) U45.H10(VCCINT) U45.J7(VCCINT) U45.J9(VCCINT) U45.J11(VCCBRAM) U45.K8(VCCINT) U45.L7(VCCINT) U45.L11(VCCBRAM) U45.M8(VCCINT) U45.N7(VCCINT) U45.N11(VCCBRAM) U45.P8(VCCINT) U45.P10(VCCINT) U45.R7(VCCINT) U45.R9(VCCINT) U45.T8(VCCINT) U45.T10(VCCINT)  [also labelled VCCINT]  [project net VCC1V0]
VCCO_15: U45.G19(VCCO_15) U45.H16(VCCO_15) U45.J13(VCCO_15) U45.K20(VCCO_15) U45.L17(VCCO_15) U45.N21(VCCO_15)  [project net VCC2V5]
XADCGND: U45.K9(GNDADC_0)
XADCVCC: U45.K10(VCCADC_0)
ACLK: U45.B2(IO_L2N_T0_AD12N_35) ; port ACLK  [project net CLOCK.ACLK]
ACNV: U45.B1(IO_L1P_T0_AD4P_35) ; port ACNV  [project net CLOCK.ACNV]
AIN: U45.A1(IO_L1N_T0_AD4N_35) ; port AIN  [project net CLOCK.AIN]
ASYNC0: U45.Y3(IO_L9P_T1_DQS_34) ; port ASYNC0  [project net APWR1.SYNC_DIFF]
ASYNC1: U45.AA1(IO_L7P_T1_34) ; port ASYNC1  [project net APWR2.SYNC_DUAL]
CLKAUX_N: U45.H19(IO_L12N_T1_MRCC_15) ; port EXTCLK_2  [project net EXTCLK.CAUX_N]
CLKAUX_P: U45.J19(IO_L12P_T1_MRCC_15) ; port EXTCLK_1  [project net EXTCLK.CAUX_P]
CLKE_N: U45.J21(IO_L11N_T1_SRCC_15) ; port CLKE_N
CLKE_P: U45.J20(IO_L11P_T1_SRCC_15) ; port CLKE_P
CLKO_N: U45.L20(IO_L14N_T2_SRCC_15) ; port CLKO_N
CLKO_P: U45.L19(IO_L14P_T2_SRCC_15) ; port CLKO_P
CNTROUT_N: U45.G16(IO_L2N_T0_AD8N_15) ; port CNTROUT_N  [project net CLOCK.CNTROUT_N]
CNTROUT_P: U45.G15(IO_L2P_T0_AD8P_15) ; port CNTROUT_P  [project net CLOCK.CNTROUT_P]
DAC1_BCLK: U45.AA20(IO_L8P_T1_D11_14) ; port BCLK_1  [project net DAC1.BCLK]
DAC1_D0: U45.W20(IO_L12N_T1_MRCC_14) ; port D0_1  [project net DAC1.D0]
DAC1_D1: U45.AB21(IO_L10P_T1_D14_14) ; port D1_1  [project net DAC1.D1]
DAC1_D2: U45.AB22(IO_L10N_T1_D15_14) ; port D2_1  [project net DAC1.D2]
DAC1_D3: U45.AA21(IO_L8N_T1_D12_14) ; port D3_1  [project net DAC1.D3]
DAC1_DCLK_N: U45.M22(IO_L15N_T2_DQS_ADV_B_15) ; port DCLK_N_1  [project net DAC1.DCLK_N]
DAC1_DCLK_P: U45.N22(IO_L15P_T2_DQS_15) ; port DCLK_P_1  [project net DAC1.DCLK_P]
DAC1_LRCK: U45.AB20(IO_L15N_T2_DQS_DOUT_CSO_B_14) ; port LRCK_1  [project net DAC1.LRCK]
DAC1_RST: U45.AA19(IO_L15P_T2_DQS_RDWR_B_14) ; port RST_1  [project net DAC1.RST]
DAC1_SCL: U45.Y18(IO_L13P_T2_MRCC_14) ; port SCL_1  [project net DAC1.SCL]
DAC1_SDA: U45.AA18(IO_L17P_T2_A14_D30_14) ; port SDA_1  [project net DAC1.SDA]
DAC2_BCLK: U45.W22(IO_L7N_T1_D10_14) ; port BCLK_2  [project net DAC2.BCLK]
DAC2_D0: U45.U20(IO_L11P_T1_SRCC_14) ; port D0_2  [project net DAC2.D0]
DAC2_D1: U45.T21(IO_L4P_T0_D04_14) ; port D1_2  [project net DAC2.D1]
DAC2_D2: U45.R19(IO_L5N_T0_D07_14) ; port D2_2  [project net DAC2.D2]
DAC2_D3: U45.P20(IO_0_14) ; port D3_2  [project net DAC2.D3]
DAC2_DCLK_N: U45.L21(IO_L10N_T1_AD11N_15) ; port DCLK_N_2  [project net DAC2.DCLK_N]
DAC2_DCLK_P: U45.M21(IO_L10P_T1_AD11P_15) ; port DCLK_P_2  [project net DAC2.DCLK_P]
DAC2_LRCK: U45.V20(IO_L11N_T1_SRCC_14) ; port LRCK_2  [project net DAC2.LRCK]
DAC2_RST: U45.W21(IO_L7P_T1_D09_14) ; port RST_2  [project net DAC2.RST]
DAC2_SCL: U45.Y22(IO_L9N_T1_DQS_D13_14) ; port SCL_2  [project net DAC2.SCL]
DAC2_SDA: U45.Y21(IO_L9P_T1_DQS_14) ; port SDA_2  [project net DAC2.SDA]
DAC3_BCLK: U45.F20(IO_L18N_T2_16) ; port BCLK_3  [project net DAC3.BCLK]
DAC3_D0: U45.D22(IO_L22N_T3_16) ; port D0_3  [project net DAC3.D0]
DAC3_D1: U45.D21(IO_L23N_T3_16) ; port D1_3  [project net DAC3.D1]
DAC3_D2: U45.C22(IO_L20P_T3_16) ; port D2_3  [project net DAC3.D2]
DAC3_D3: U45.B21(IO_L21P_T3_DQS_16) ; port D3_3  [project net DAC3.D3]
DAC3_DCLK_N: U45.K22(IO_L9N_T1_DQS_AD3N_15) ; port DCLK_N_3  [project net DAC3.DCLK_N]
DAC3_DCLK_P: U45.K21(IO_L9P_T1_DQS_AD3P_15) ; port DCLK_P_3  [project net DAC3.DCLK_P]
DAC3_LRCK: U45.E21(IO_L23P_T3_16) ; port LRCK_3  [project net DAC3.LRCK]
DAC3_RST: U45.F21(IO_25_16) ; port RST_3  [project net DAC3.RST]
DAC3_SCL: U45.G22(IO_L24N_T3_16) ; port SCL_3  [project net DAC3.SCL]
DAC3_SDA: U45.G21(IO_L24P_T3_16) ; port SDA_3  [project net DAC3.SDA]
DAC4_BCLK: U45.C20(IO_L19N_T3_VREF_16) ; port BCLK_4  [project net DAC4.BCLK]
DAC4_D0: U45.A19(IO_L17N_T2_16) ; port D0_4  [project net DAC4.D0]
DAC4_D1: U45.B18(IO_L11N_T1_SRCC_16) ; port D1_4  [project net DAC4.D1]
DAC4_D2: U45.A18(IO_L17P_T2_16) ; port D2_4  [project net DAC4.D2]
DAC4_D3: U45.B17(IO_L11P_T1_SRCC_16) ; port D3_4  [project net DAC4.D3]
DAC4_DCLK_N: U45.H22(IO_L7N_T1_AD2N_15) ; port DCLK_N_4  [project net DAC4.DCLK_N]
DAC4_DCLK_P: U45.J22(IO_L7P_T1_AD2P_15) ; port DCLK_P_4  [project net DAC4.DCLK_P]
DAC4_LRCK: U45.C19(IO_L13N_T2_MRCC_16) ; port LRCK_4  [project net DAC4.LRCK]
DAC4_RST: U45.A21(IO_L21N_T3_DQS_16) ; port RST_4  [project net DAC4.RST]
DAC4_SCL: U45.B20(IO_L16P_T2_16) ; port SCL_4  [project net DAC4.SCL]
DAC4_SDA: U45.B22(IO_L20N_T3_16) ; port SDA_4  [project net DAC4.SDA]
EMCLK_EN: U45.U21(IO_L4N_T0_D05_14) ; port EMCLK_EN  [project net SQSPI.EMCLK_EN]
EXTCLK_1: U45.W5(IO_L15N_T2_DQS_34)
EXTCLK_2: U45.W4(IO_L12N_T1_MRCC_34)
LED_A: U45.V19(IO_L14N_T2_SRCC_14) ; port LED_A
LED_B: U45.V18(IO_L14P_T2_SRCC_14) ; port LED_B
LED_C: U45.V17(IO_L16P_T2_CSI_B_14) ; port LED_C
LED_D: U45.U18(IO_L18N_T2_A11_D27_14) ; port LED_D
LED_PG: U45.W19(IO_L12P_T1_MRCC_14) ; port LED_PG
LEDIN: U45.AB3(IO_L8P_T1_34)
OSCCLK_N: U45.K19(IO_L13N_T2_MRCC_15) ; port OSCCLK_N  [project net CLOCK.OSCCLK_N]
OSCCLK_P: U45.K18(IO_L13P_T2_MRCC_15) ; port OSCCLK_P  [project net CLOCK.OSCCLK_P]
PCIE_CLK_N: U45.E6(MGTREFCLK0N_216) ; port PCIE_CLK_N  [project net PCIE.PCIE_CLK_N]
PCIE_CLK_P: U45.F6(MGTREFCLK0P_216) ; port PCIE_CLK_P  [project net PCIE.PCIE_CLK_P]
PCIE_PERST: U45.A15(IO_L9P_T1_DQS_16) ; port PCIE_PERST  [project net PCIE.PCIE_PERST]
PCIE_PWRGD: U45.T1(IO_L1P_T0_34) ; port PCIE_PWRGD  [project net PCIE.PCIE_PWRGD]
PCIE_RX0_N: U45.A8(MGTPRXN0_216) ; port PCIE_RX0_P  [project net PCIE.PCIE_RX0_P]
PCIE_RX0_P: U45.B8(MGTPRXP0_216) ; port PCIE_RX0_N  [project net PCIE.PCIE_RX0_N]
PCIE_RX1_N: U45.C11(MGTPRXN1_216) ; port PCIE_RX1_P  [project net PCIE.PCIE_RX1_P]
PCIE_RX1_P: U45.D11(MGTPRXP1_216) ; port PCIE_RX1_N  [project net PCIE.PCIE_RX1_N]
PCIE_RX2_N: U45.A10(MGTPRXN2_216) ; port PCIE_RX2_P  [project net PCIE.PCIE_RX2_P]
PCIE_RX2_P: U45.B10(MGTPRXP2_216) ; port PCIE_RX2_N  [project net PCIE.PCIE_RX2_N]
PCIE_RX3_N: U45.C9(MGTPRXN3_216) ; port PCIE_RX3_P  [project net PCIE.PCIE_RX3_P]
PCIE_RX3_P: U45.D9(MGTPRXP3_216) ; port PCIE_RX3_N  [project net PCIE.PCIE_RX3_N]
PCIE_TX0_N: U45.A4(MGTPTXN0_216) ; port PCIE_TX0_P  [project net PCIE.PCIE_TX0_P]
PCIE_TX0_P: U45.B4(MGTPTXP0_216) ; port PCIE_TX0_N  [project net PCIE.PCIE_TX0_N]
PCIE_TX1_N: U45.C5(MGTPTXN1_216) ; port PCIE_TX1_P  [project net PCIE.PCIE_TX1_P]
PCIE_TX1_P: U45.D5(MGTPTXP1_216) ; port PCIE_TX1_N  [project net PCIE.PCIE_TX1_N]
PCIE_TX2_N: U45.A6(MGTPTXN2_216) ; port PCIE_TX2_P  [project net PCIE.PCIE_TX2_P]
PCIE_TX2_P: U45.B6(MGTPTXP2_216) ; port PCIE_TX2_N  [project net PCIE.PCIE_TX2_N]
PCIE_TX3_N: U45.C7(MGTPTXN3_216) ; port PCIE_TX3_P  [project net PCIE.PCIE_TX3_P]
PCIE_TX3_P: U45.D7(MGTPTXP3_216) ; port PCIE_TX3_N  [project net PCIE.PCIE_TX3_N]
PG0: U45.U1(IO_L1N_T0_34)
PG1: U45.V3(IO_L6N_T0_VREF_34)
PG2: U45.U2(IO_L2P_T0_34)
PG3: U45.Y2(IO_L4N_T0_34)
PG4: U45.AA3(IO_L9N_T1_DQS_34)
PG5: U45.AB1(IO_L7N_T1_34)
PG6: U45.W2(IO_L4P_T0_34)
PG7: U45.V2(IO_L2N_T0_34)
PG8: U45.R4(IO_L13P_T2_MRCC_34)
PG9: U45.R2(IO_L3N_T0_DQS_34)
PG10: U45.R3(IO_L3P_T0_DQS_34)
PUDC_B: U45.U22(IO_L3P_T0_DQS_PUDC_B_14) ; port PUDC_B  [project net SQSPI.PUDC_B]
PWRSYNC: U45.AB2(IO_L8N_T1_34) ; port PWRSYNC  [project net POWER.PWRSYNC]
QSPI_CS: U45.T19(IO_L6P_T0_FCS_B_14) ; port QSPI_CS  [project net SQSPI.QSPI_CS]
QSPI_DQ0: U45.P22(IO_L1P_T0_D00_MOSI_14) ; port QSPI_DQ0  [project net SQSPI.QSPI_DQ0]
QSPI_DQ1: U45.R22(IO_L1N_T0_D01_DIN_14) ; port QSPI_DQ1  [project net SQSPI.QSPI_DQ1]
QSPI_DQ2: U45.P21(IO_L2P_T0_D02_14) ; port QSPI_DQ2  [project net SQSPI.QSPI_DQ2]
QSPI_DQ3: U45.R21(IO_L2N_T0_D03_14) ; port QSPI_DQ3  [project net SQSPI.QSPI_DQ3]
QSPI_EMCLK: U45.V22(IO_L3N_T0_DQS_EMCCLK_14) ; port QSPI_EMCLK  [project net SQSPI.QSPI_EMCLK]
SW1: U45.AA5(IO_L10P_T1_34)
SW2: U45.AB5(IO_L10N_T1_34)
SW3: U45.AA6(IO_L18N_T2_34)
SW4: U45.AB6(IO_L20N_T3_34)
SW5: U45.AB7(IO_L20P_T3_34)
SW6: U45.AA8(IO_L22P_T3_34)
SW7: U45.AB8(IO_L22N_T3_34)
SW8: U45.Y9(IO_L24N_T3_34)
SYNC_N: U45.G13(IO_L1N_T0_AD0N_15) ; port SYNC_N  [project net CLOCK.SYNC_N]
SYNC_P: U45.H13(IO_L1P_T0_AD0P_15) ; port SYNC_P  [project net CLOCK.SYNC_P]
TRIG_N: U45.G20(IO_L8N_T1_AD10N_15) ; port TRIG_N  [project net EXT.TRIGout_N]
TRIG_P: U45.H20(IO_L8P_T1_AD10P_15) ; port TRIG_P  [project net EXT.TRIGout_P]
XADCMUX0: U45.K1(IO_L7P_T1_AD6P_35)  [project net XMUX0]
XADCMUX1: U45.L1(IO_L15N_T2_DQS_35)  [project net XMUX1]
XADCMUX2: U45.M1(IO_L15P_T2_DQS_35)  [project net XMUX2]
XADCMUX3: U45.J1(IO_L7N_T1_AD6N_35)  [project net XMUX3]
NetR287_1: R287.1 U45.F8(MGTRREF_216)

Not connected (* = marked no-connect by the designer): U45 A13(IO_L10P_T1_16) A14(IO_L10N_T1_16) A16(IO_L9N_T1_DQS_16) A20(IO_L16N_T2_16) AA4(IO_L11N_T1_SRCC_34) AA9(IO_L8P_T1_13) AA10(IO_L9P_T1_DQS_13) AA11(IO_L9N_T1_DQS_13) AA13(IO_L3P_T0_DQS_13) AA14(IO_L5N_T0_13) AA15(IO_L4P_T0_13) AA16(IO_L1N_T0_13) AB10(IO_L8N_T1_13) AB11(IO_L7P_T1_13) AB12(IO_L7N_T1_13) AB13(IO_L3N_T0_DQS_13) AB15(IO_L4N_T0_13) AB16(IO_L2P_T0_13) AB17(IO_L2N_T0_13) AB18(IO_L17N_T2_A13_D29_14) B13(IO_L8N_T1_16) B15(IO_L7P_T1_16) B16(IO_L7N_T1_16) C2(IO_L2P_T0_AD12P_35) C13(IO_L8P_T1_16) C14(IO_L3P_T0_DQS_16) C15(IO_L3N_T0_DQS_16) C17(IO_L12N_T1_MRCC_16) C18(IO_L13P_T2_MRCC_16) D1(IO_L3N_T0_DQS_AD5N_35) D2(IO_L4N_T0_35) D14(IO_L6P_T0_16) D15(IO_L6N_T0_VREF_16) D16(IO_L5N_T0_16) D17(IO_L12P_T1_MRCC_16) D19(IO_L14N_T2_SRCC_16) D20(IO_L19P_T3_16) E1(IO_L3P_T0_DQS_AD5P_35) E2(IO_L4P_T0_35) E3(IO_L6N_T0_VREF_35) E10(MGTREFCLK1N_216)* E13(IO_L4P_T0_16) E14(IO_L4N_T0_16) E16(IO_L5P_T0_16) E17(IO_L2N_T0_16) E18(IO_L15N_T2_DQS_16) E19(IO_L14P_T2_SRCC_16) E22(IO_L22P_T3_16) F1(IO_L5N_T0_AD13N_35) F3(IO_L6P_T0_35) F4(IO_0_35) F10(MGTREFCLK1P_216)* F13(IO_L1P_T0_16) F14(IO_L1N_T0_16) F15(IO_0_16) F16(IO_L2P_T0_16) F18(IO_L15P_T2_DQS_16) F19(IO_L18P_T2_16) G1(IO_L5P_T0_AD13P_35) G2(IO_L8N_T1_AD14N_35) G3(IO_L11N_T1_SRCC_35) G4(IO_L12N_T1_MRCC_35) G17(IO_L4P_T0_15) G18(IO_L4N_T0_15) H2(IO_L8P_T1_AD14P_35) H3(IO_L11P_T1_SRCC_35) H4(IO_L12P_T1_MRCC_35) H5(IO_L10N_T1_AD15N_35) H14(IO_L3N_T0_DQS_AD1N_15) H15(IO_L5N_T0_AD9N_15) H17(IO_L6P_T0_15) H18(IO_L6N_T0_VREF_15) J2(IO_L9N_T1_DQS_AD7N_35) J4(IO_L13N_T2_MRCC_35) J5(IO_L10P_T1_AD15P_35) J6(IO_L17N_T2_35) J14(IO_L3P_T0_DQS_AD1P_15) J15(IO_L5P_T0_AD9P_15) J16(IO_0_15) J17(IO_L21N_T3_DQS_A18_15) K2(IO_L9P_T1_DQS_AD7P_35) K3(IO_L14N_T2_SRCC_35) K4(IO_L13P_T2_MRCC_35) K6(IO_L17P_T2_35) K13(IO_L19P_T3_A22_15) K14(IO_L19N_T3_A21_VREF_15) K16(IO_L23N_T3_FWE_B_15) K17(IO_L21P_T3_DQS_15) L3(IO_L14P_T2_SRCC_35) L4(IO_L18N_T2_35) L5(IO_L18P_T2_35) L6(IO_25_35) L13(IO_L20N_T3_A19_15) L14(IO_L22P_T3_A17_15) L15(IO_L22N_T3_A16_15) L16(IO_L23P_T3_FOE_B_15) L18(IO_L16N_T2_A27_15) M2(IO_L16N_T2_35) M3(IO_L16P_T2_35) M5(IO_L23N_T3_35) M6(IO_L23P_T3_35) M13(IO_L20P_T3_A20_15) M15(IO_L24P_T3_RS1_15) M16(IO_L24N_T3_RS0_15) M17(IO_25_15) M18(IO_L16P_T2_A28_15) M20(IO_L18N_T2_A23_15) N2(IO_L22N_T3_35) N3(IO_L19N_T3_VREF_35) N4(IO_L19P_T3_35) N5(IO_L24N_T3_35) N13(IO_L23P_T3_A03_D19_14) N14(IO_L23N_T3_A02_D18_14) N15(IO_25_14) N17(IO_L21P_T3_DQS_14) N18(IO_L17P_T2_A26_15) N19(IO_L17N_T2_A25_15) N20(IO_L18P_T2_A24_15) P1(IO_L20N_T3_35) P2(IO_L22P_T3_35) P4(IO_L21N_T3_DQS_35) P5(IO_L21P_T3_DQS_35) P6(IO_L24P_T3_35) P14(IO_L19P_T3_A10_D26_14) P15(IO_L22P_T3_A05_D21_14) P16(IO_L24P_T3_A01_D17_14) P17(IO_L21N_T3_DQS_A06_D22_14) P19(IO_L5P_T0_D06_14) R1(IO_L20P_T3_35) R6(IO_L17P_T2_34) R14(IO_L19N_T3_A09_D25_VREF_14) R16(IO_L22N_T3_A04_D20_14) R17(IO_L24N_T3_A00_D16_14) R18(IO_L20P_T3_A08_D24_14) T3(IO_0_34) T4(IO_L13N_T2_MRCC_34) T5(IO_L14P_T2_SRCC_34) T6(IO_L17N_T2_34) T14(IO_L15P_T2_DQS_13) T15(IO_L15N_T2_DQS_13) T16(IO_L17P_T2_13) T18(IO_L20N_T3_A07_D23_14) T20(IO_L6N_T0_D08_VREF_14) U3(IO_L6P_T0_34) U5(IO_L14N_T2_SRCC_34) U6(IO_L16P_T2_34) U7(IO_25_34) U15(IO_L14P_T2_SRCC_13) U16(IO_L17N_T2_13) U17(IO_L18P_T2_A12_D28_14) V4(IO_L12P_T1_MRCC_34) V5(IO_L16N_T2_34) V7(IO_L19P_T3_34) V8(IO_L21N_T3_DQS_34) V9(IO_L21P_T3_DQS_34) V10(IO_L10P_T1_13) V13(IO_L13P_T2_MRCC_13) V14(IO_L13N_T2_MRCC_13) V15(IO_L14N_T2_SRCC_13) W1(IO_L5P_T0_34) W6(IO_L15P_T2_DQS_34) W7(IO_L19N_T3_VREF_34) W9(IO_L24P_T3_34) W10(IO_L10N_T1_13) W11(IO_L12P_T1_MRCC_13) W12(IO_L12N_T1_MRCC_13) W14(IO_L6P_T0_13) W15(IO_L16P_T2_13) W16(IO_L16N_T2_13) W17(IO_L16N_T2_A15_D31_14) Y1(IO_L5N_T0_34) Y4(IO_L11P_T1_SRCC_34) Y6(IO_L18P_T2_34) Y7(IO_L23N_T3_34) Y8(IO_L23P_T3_34) Y11(IO_L11P_T1_SRCC_13) Y12(IO_L11N_T1_SRCC_13) Y13(IO_L5P_T0_13) Y14(IO_L6N_T0_VREF_13) Y16(IO_L1P_T0_13) Y17(IO_0_13) Y19(IO_L13N_T2_MRCC_14)

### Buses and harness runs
bus PG[9..0] = port PG[9..0]
bus SW[8..1] = port SW[8..1]
bus XADCMUX[3..0] = port XADCMUX[3..0]

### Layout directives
differential pair: DAC1.DCLK_N, DAC1.DCLK_P, DAC2.DCLK_N, DAC2.DCLK_P, DAC3.DCLK_N, DAC3.DCLK_P, DAC4.DCLK_N, DAC4.DCLK_P, PCIE.PCIE_CLK_N, PCIE.PCIE_CLK_P, PCIE.PCIE_RX0_N, PCIE.PCIE_RX0_P, PCIE.PCIE_RX1_N, PCIE.PCIE_RX1_P, PCIE.PCIE_RX2_N, PCIE.PCIE_RX2_P, PCIE.PCIE_RX3_N, PCIE.PCIE_RX3_P, PCIE.PCIE_TX0_N, PCIE.PCIE_TX0_P, PCIE.PCIE_TX1_N, PCIE.PCIE_TX1_P, PCIE.PCIE_TX2_N, PCIE.PCIE_TX2_P, PCIE.PCIE_TX3_N, PCIE.PCIE_TX3_P

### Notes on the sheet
- DAC 1
- DAC3
- DAC2
- DAC4
- FPGA xADC
- FPGA Config
- FPGA Flash
- PCIe Connector
- Optional External Clock
- Phase Detector

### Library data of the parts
R287 = ChipRes1: R0402 100; Part Number: RR0510P-101-D
U45 = CMP-0364-00012-3: Artix-7 FPGA, 285 User I/Os, 4 GTP, 484-Ball BGA, Speed Grade 2, Industrial Grade, Pb-Free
